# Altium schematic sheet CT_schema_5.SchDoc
size 479 x 328 mm
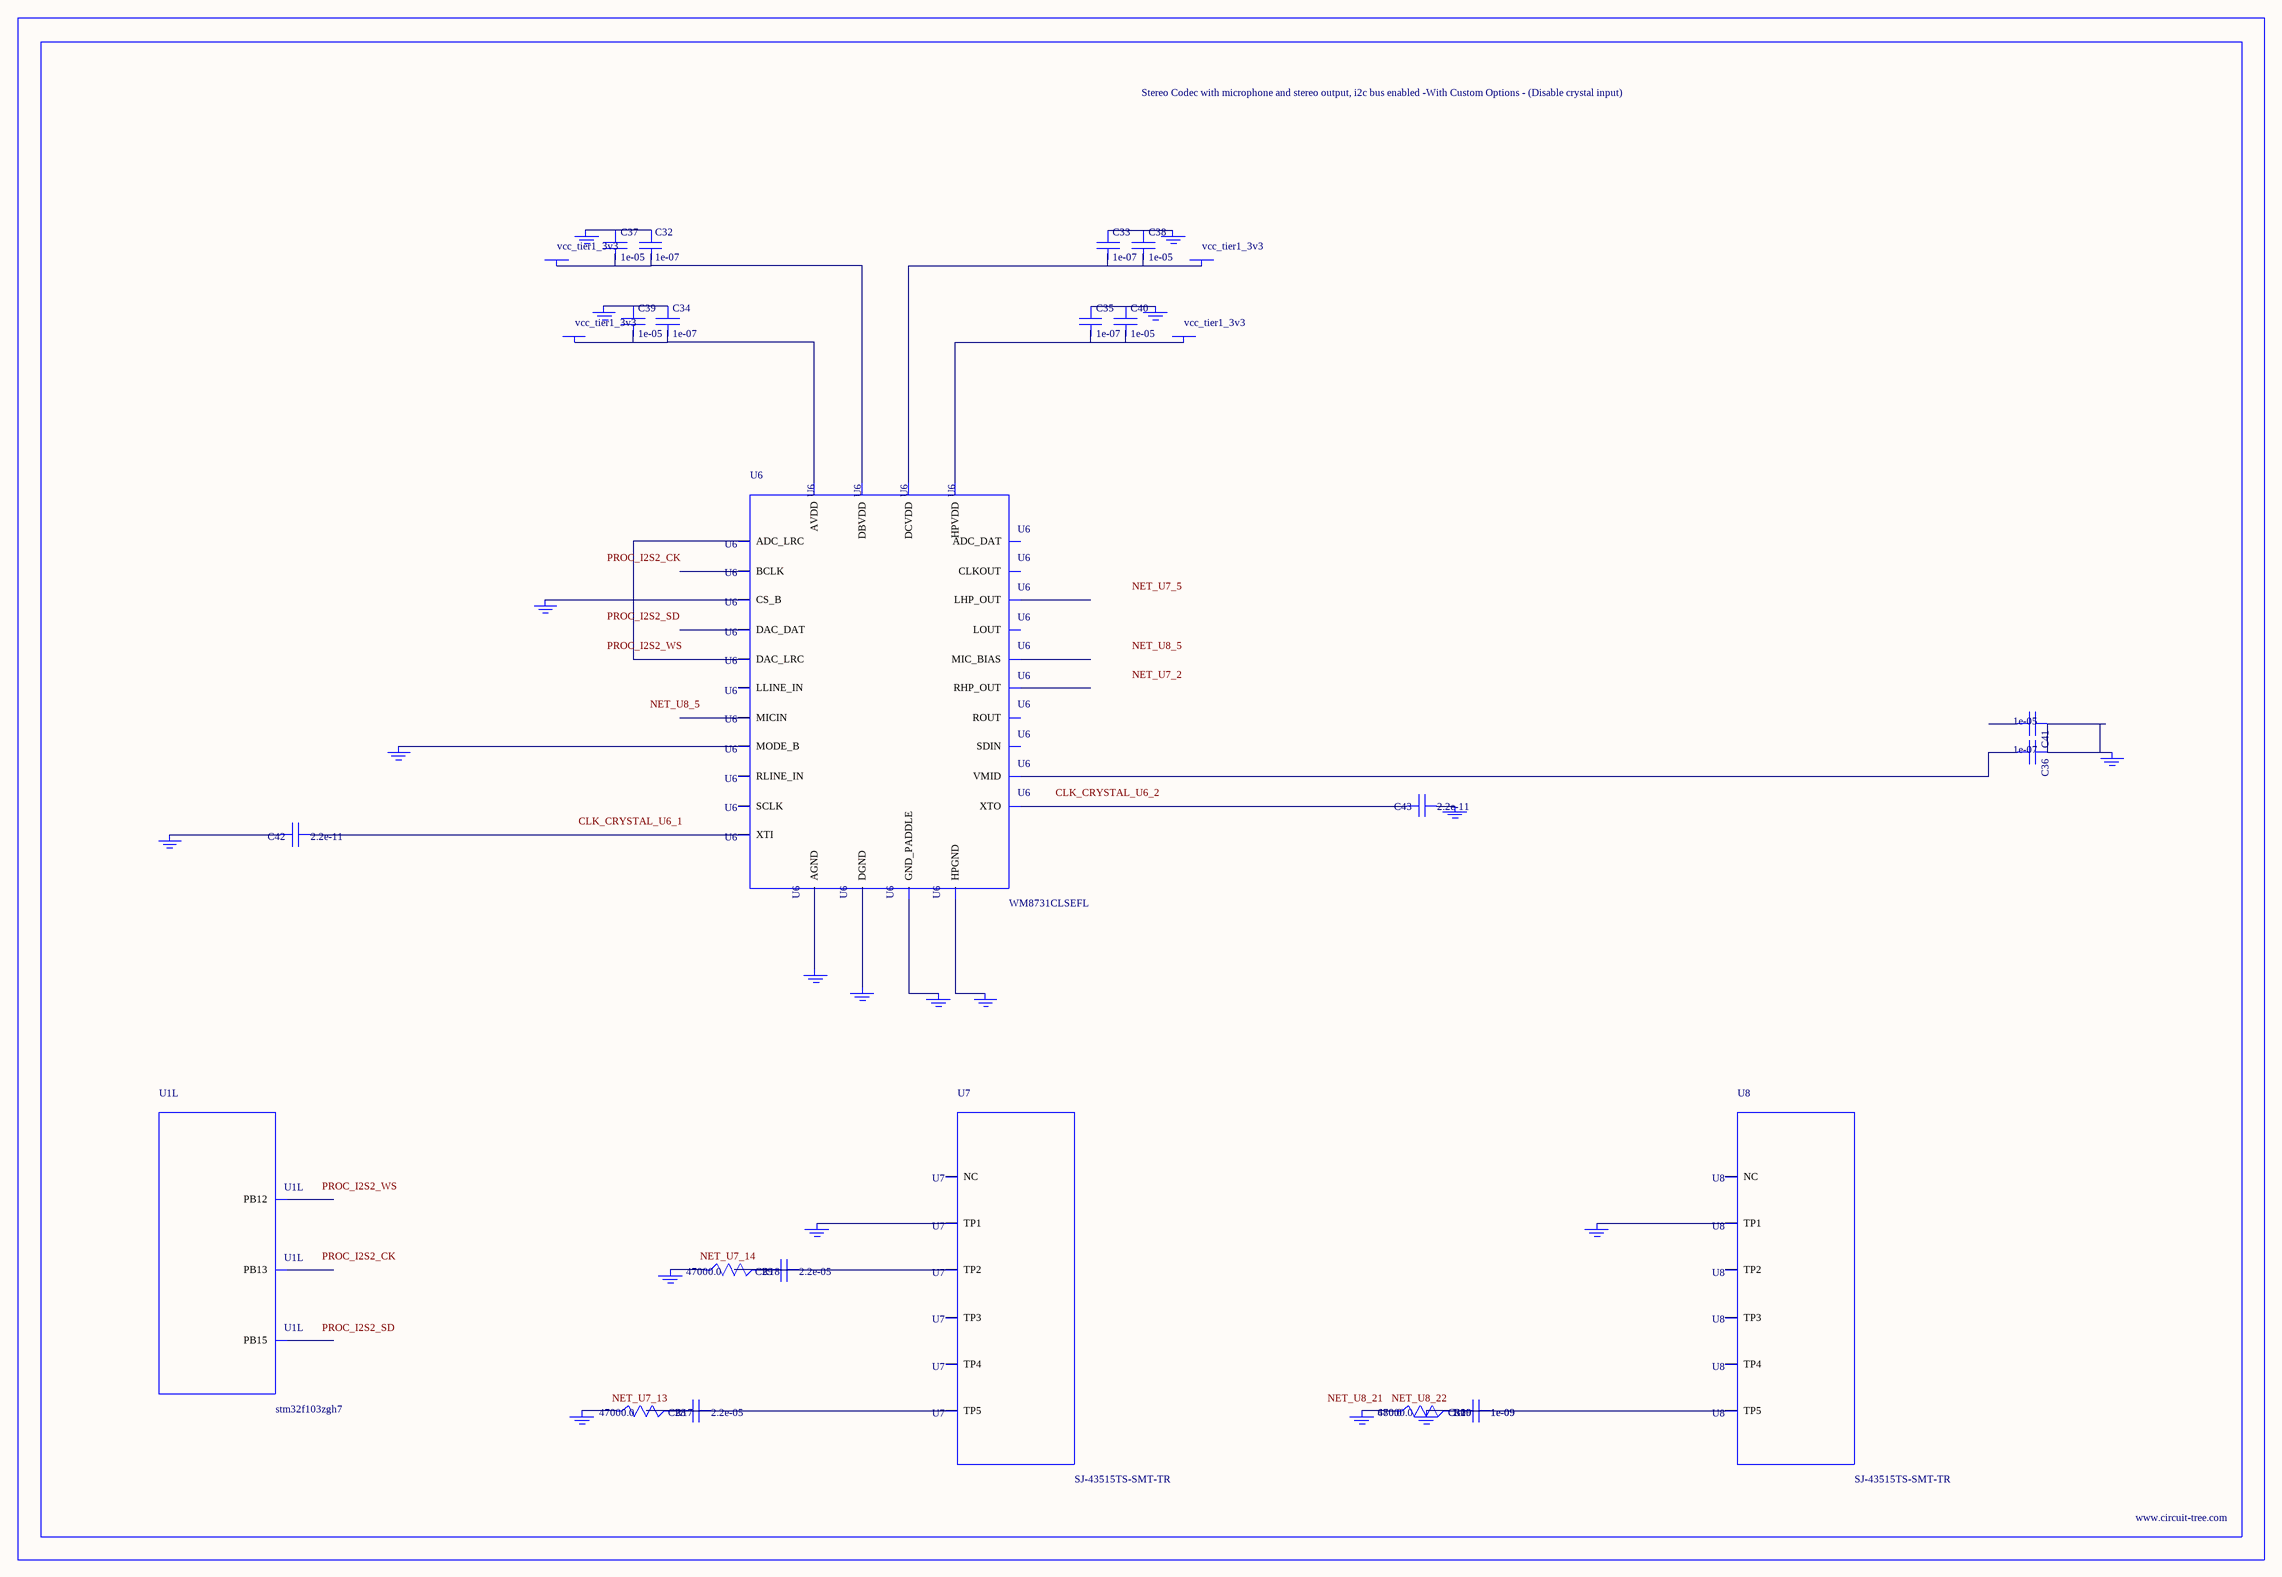
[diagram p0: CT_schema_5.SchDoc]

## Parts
BORDER4  (no value)
C28  2.2e-05  [C1210]
C29  2.2e-05  [C1210]
C30  1e-09  [C0402]
C31  1e-09  [C0402]
C32  1e-07  [C0402]
C33  1e-07  [C0402]
C34  1e-07  [C0402]
C35  1e-07  [C0402]
C36  1e-07  [C0402]
C37  1e-05  [C0805]
C38  1e-05  [C0805]
C39  1e-05  [C0805]
C40  1e-05  [C0805]
C41  1e-05  [C0805]
C42  2.2e-11  [C0402]
C43  2.2e-11  [C0402]
GND_INSTANCE_4_0  (no value)
GND_INSTANCE_4_1  (no value)
GND_INSTANCE_4_2  (no value)
GND_INSTANCE_4_3  (no value)
GND_INSTANCE_4_4  (no value)
GND_INSTANCE_4_5  (no value)
GND_INSTANCE_4_6  (no value)
GND_INSTANCE_4_7  (no value)
GND_INSTANCE_4_8  (no value)
GND_INSTANCE_4_9  (no value)
GND_INSTANCE_4_10  (no value)
GND_INSTANCE_4_11  (no value)
GND_INSTANCE_4_12  (no value)
GND_INSTANCE_4_13  (no value)
GND_INSTANCE_4_14  (no value)
GND_INSTANCE_4_15  (no value)
GND_INSTANCE_4_16  (no value)
GND_INSTANCE_4_17  (no value)
GND_INSTANCE_4_18  (no value)
POWER_INSTANCE_4_0  vcc_tier1_3v3
POWER_INSTANCE_4_1  vcc_tier1_3v3
POWER_INSTANCE_4_2  vcc_tier1_3v3
POWER_INSTANCE_4_3  vcc_tier1_3v3
R17  47000.0  [R0603]
R18  47000.0  [R0603]
R19  47000.0  [R0603]
R20  680.0  [R0603]
U1  stm32f103zgh7  [LFBGA144]  (part L of 12)
U6  WM8731CLSEFL  [QFN-28]
U7  SJ-43515TS-SMT-TR  [SJ-43515TS-SMT-TR]
U8  SJ-43515TS-SMT-TR  [SJ-43515TS-SMT-TR]

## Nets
NetC28_1: C28.1 C28.2 R17.2 U7.5(TP5)
NetC29_1: C29.1 C29.2 R18.2 U7.2(TP2)
NetC30_1: C30.1 C30.2 C31.1 C31.2 GND_INSTANCE_4_18.0(GND) R19.2 R20.2 U8.5(TP5)
NetC32_1: C32.1 C37.1 GND_INSTANCE_4_3.0(GND)
NetC32_2: C32.2 C37.2 POWER_INSTANCE_4_1.0(PWR) U6.5(DBVDD)
NetC33_1: C33.1 C38.1 GND_INSTANCE_4_2.0(GND)
NetC33_2: C33.2 C38.2 POWER_INSTANCE_4_0.0(PWR) U6.3(DCVDD)
NetC34_1: C34.1 C39.1 GND_INSTANCE_4_6.0(GND)
NetC34_2: C34.2 C39.2 POWER_INSTANCE_4_3.0(PWR) U6.18(AVDD)
NetC35_1: C35.1 C40.1 GND_INSTANCE_4_4.0(GND)
NetC35_2: C35.2 C40.2 POWER_INSTANCE_4_2.0(PWR) U6.12(HPVDD)
NetC36_1: C36.1 C41.1 GND_INSTANCE_4_7.0(GND)
NetC36_2: C36.2 U6.20(VMID)
NetC42_1: C42.1 U6.1(XTI)
NetC42_2: C42.2 GND_INSTANCE_4_0.0(GND)
NetC43_1: C43.1 GND_INSTANCE_4_1.0(GND)
NetC43_2: C43.2 U6.2(XTO)
NetGND_INSTANCE_4_5_0: GND_INSTANCE_4_5.0(GND) U6.15(HPGND)
NetGND_INSTANCE_4_8_0: GND_INSTANCE_4_8.0(GND) U6.25(MODE_B)
NetGND_INSTANCE_4_9_0: GND_INSTANCE_4_9.0(GND) U6.26(CS_B)
NetGND_INSTANCE_4_10_0: GND_INSTANCE_4_10.0(GND) U6.29(GND_PADDLE)
NetGND_INSTANCE_4_11_0: GND_INSTANCE_4_11.0(GND) U6.4(DGND)
NetGND_INSTANCE_4_12_0: GND_INSTANCE_4_12.0(GND) U6.19(AGND)
NetGND_INSTANCE_4_13_0: GND_INSTANCE_4_13.0(GND) U7.1(TP1)
NetGND_INSTANCE_4_14_0: GND_INSTANCE_4_14.0(GND) R18.1
NetGND_INSTANCE_4_15_0: GND_INSTANCE_4_15.0(GND) R17.1
NetGND_INSTANCE_4_16_0: GND_INSTANCE_4_16.0(GND) U8.1(TP1)
NetGND_INSTANCE_4_17_0: GND_INSTANCE_4_17.0(GND) R19.1 R20.1
NetU6_9: U6.9(DAC_LRC) U6.11(ADC_LRC)

Not connected (* = marked no-connect by the designer): C41 2; U1 L12(PB15) M11(PB12) M12(PB13); U6 6(CLKOUT) 7(BCLK) 8(DAC_DAT) 10(ADC_DAT) 13(LHP_OUT) 14(RHP_OUT) 16(LOUT) 17(ROUT) 21(MIC_BIAS) 22(MICIN) 23(RLINE_IN) 24(LLINE_IN) 27(SDIN) 28(SCLK); U7 3(TP3) 4(TP4) 6(NC); U8 2(TP2) 3(TP3) 4(TP4) 6(NC)

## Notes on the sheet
- Labels drawn without touching a wire or pin: CLK_CRYSTAL_U6_1, CLK_CRYSTAL_U6_2, NET_U7_2, NET_U7_5, NET_U7_13, NET_U7_14, NET_U8_5, NET_U8_21, NET_U8_22, PROC_I2S2_CK, PROC_I2S2_SD, PROC_I2S2_WS

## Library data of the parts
BORDER4 = BORDER_PAGE4
C28 C29 = C1210C224K5RACTU
C30 C31 = C0402C102K3RAC
C32-C36 = C0402C104K3RACTU
C37-C41 = C0805C106K8RACTU
C42 C43 = C0402C220K3RAC
GND_INSTANCE_4_0-GND_INSTANCE_4_18 = GND
POWER_INSTANCE_4_0-POWER_INSTANCE_4_3 = PWR
R17-R19 = RC0603JR-0747KL
R20 = RC0603JR-07680RL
